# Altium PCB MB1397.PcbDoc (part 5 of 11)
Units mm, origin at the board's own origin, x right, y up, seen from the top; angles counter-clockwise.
Board outline 118.24 x 172.86 mm, 6 copper layers (Top Layer, L2_GND, L3_VCC, L4_SIG, L5_GND, Bottom Layer), stack 1.631 mm thick; 819 components, 632 nets, 2875 pads, 1523 vias.
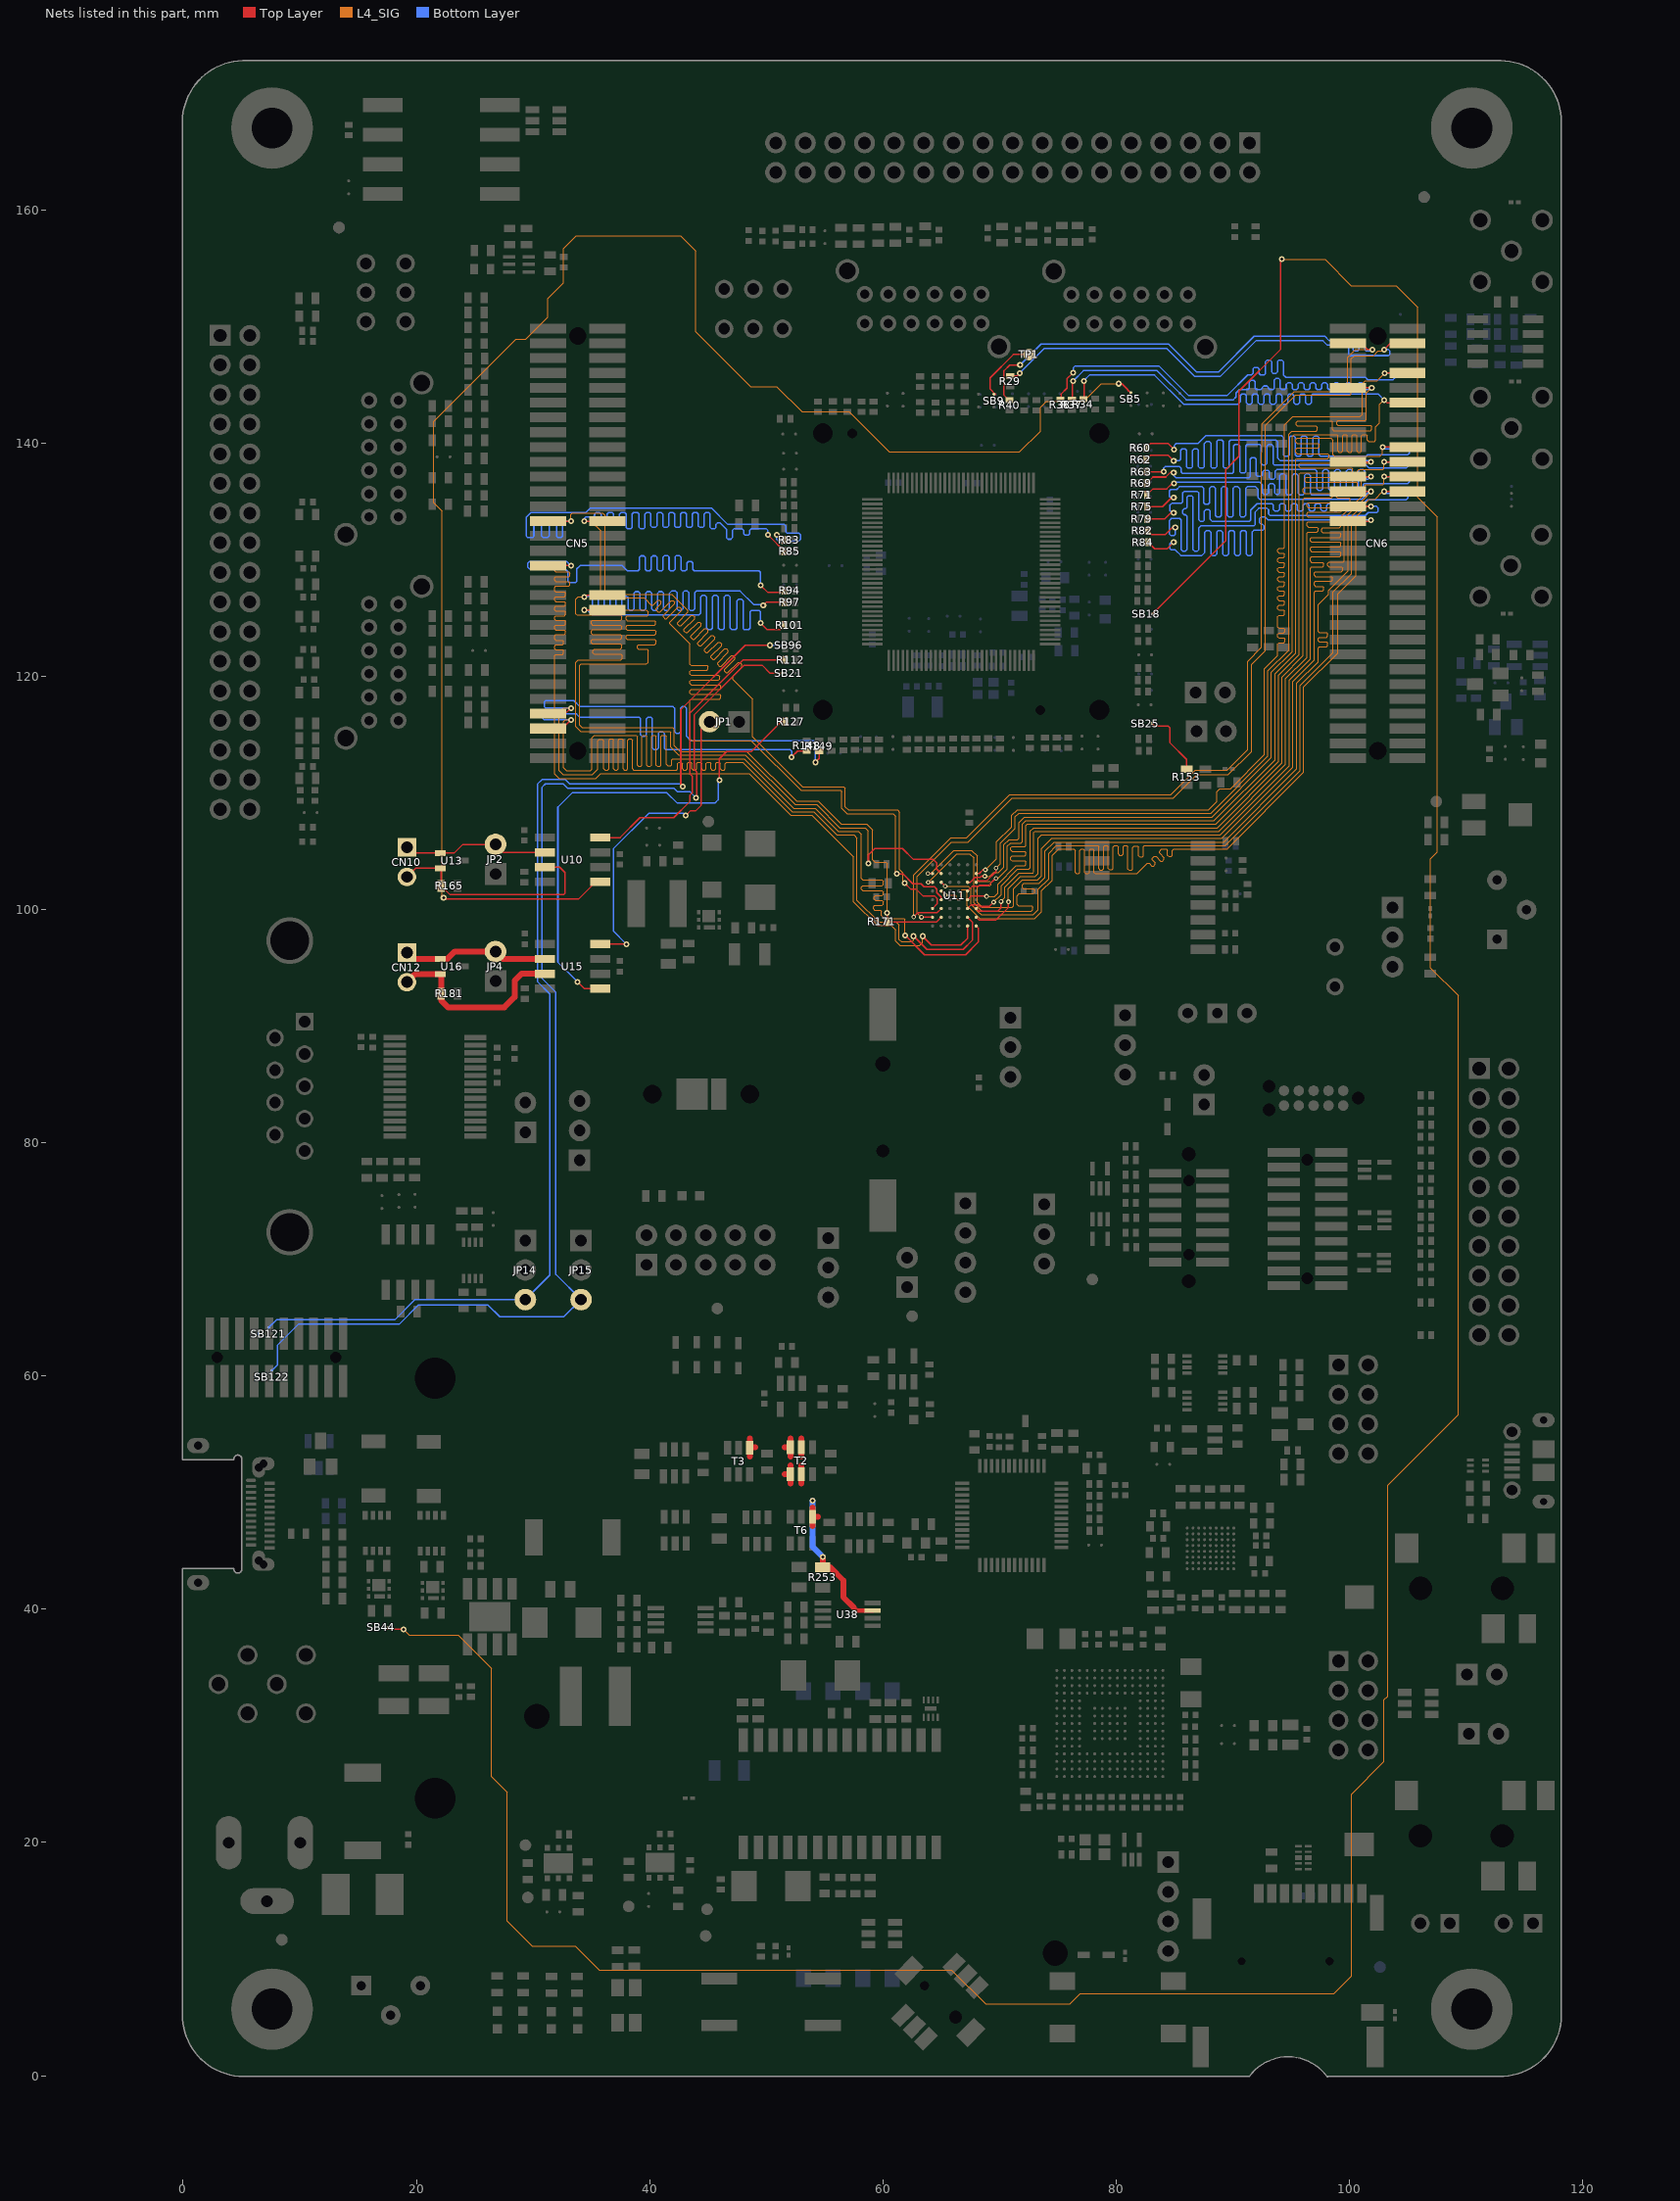
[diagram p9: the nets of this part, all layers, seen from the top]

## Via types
v1: diameter 0.508, hole 0.254, Top Layer to Bottom Layer, tented both sides, 1330 vias
v2: diameter 0.406, hole 0.203, Top Layer to Bottom Layer, tented both sides, 115 vias
v3: diameter 0.508, hole 0.254, Top Layer to Bottom Layer, 33 vias
v4: diameter 0.305, hole 0.152, Top Layer to Bottom Layer, tented both sides, 26 vias
v5: diameter 0.61, hole 0.305, Top Layer to Bottom Layer, tented both sides, 14 vias
v6: diameter 0.61, hole 0.33, Top Layer to Bottom Layer, tented both sides, 2 vias
v7: diameter 0.381, hole 0.203, Top Layer to Bottom Layer, tented both sides, 2 vias
v8: diameter 0.508, hole 0.203, Top Layer to Bottom Layer, tented both sides, 1 vias

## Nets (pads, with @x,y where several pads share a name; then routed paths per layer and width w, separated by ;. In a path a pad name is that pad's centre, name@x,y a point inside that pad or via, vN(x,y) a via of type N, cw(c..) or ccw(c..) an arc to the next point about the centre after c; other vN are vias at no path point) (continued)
CAL_D: R253.2 T2.1 T2.2 T2.5 T2.6 T3.4 T6.4 U38.3 | length 24
  Top Layer w0.381: 57.485,40.162 57.757,39.891 U38.3@59.098,39.891
  Top Layer w0.508: 48.58,53.094 T3.4@48.58,53.871 ; 48.58,54.648 T3.4@48.58,53.871 ; 49.058,53.871 T3.4@48.58,53.871 ; 51.58,51.57 T2.1@52.057,51.57 ; 51.58,53.871 T2.6@52.057,53.871 ; 52.057,50.792 T2.1@52.057,51.57 ; 52.057,52.349 T2.1@52.057,51.57 ; 52.057,53.094 T2.6@52.057,53.871 ; 52.057,54.648 T2.6@52.057,53.871 ; 53.007,50.792 53.007,52.349 ; 53.007,53.094 53.007,54.648 ; 53.957,47.147 T6.4@53.957,47.927 ; 53.957,48.705 T6.4@53.957,47.927 ; 54.435,47.925 T6.4@53.957,47.927 ; R253.2@54.836,43.594 R253.2@54.839,43.594 ; v1(54.839,44.498) R253.2@54.839,43.594 ; 57.485,40.162 56.614,41.034 56.614,42.466 55.486,43.594 R253.2@54.839,43.594
  Bottom Layer w0.508: v1(53.947,49.324) 53.947,45.387 v1(54.839,44.498)
CAN1H: CN12.1 JP4.2 U15.6 U16.1 | length 12.6
  Top Layer w0.508: CN12.1@19.186,96.307 19.718,95.773 22.672,95.773 23.292,96.393 JP4.2@26.782,96.394 27.417,95.758 U15.6@31.011,95.759
CAN1L: CN12.2 R181.1 U15.7 U16.2 | length 16.6
  Top Layer w0.508: CN12.2@19.186,93.767 CN12.2@19.186,93.767 19.893,94.473 U16.2@22.048,94.474 22.121,94.402 R181.1@22.121,92.786 ; R181.1@22.12,92.788 R181.1@22.121,92.786 ; U15.7@31.011,94.489 29.007,94.488 28.42,93.901 28.42,92.504 27.531,91.615 22.705,91.615 22.121,92.199 R181.1@22.121,92.786
CAN2H: CN10.1 JP2.2 U10.6 U13.1 | length 12.6
  Top Layer w0.127: CN10.1@19.186,105.33 19.68,104.833 23.226,104.833 23.975,105.583 JP2.2@26.782,105.584 27.465,104.899 U10.6@31.011,104.901
CAN2L: CN10.2 R165.1 U10.7 U13.2 | length 19.4
  Top Layer w0.127: CN10.2@19.186,102.79 CN10.2@19.186,102.79 19.931,103.533 22.05,103.533 22.121,103.462 R165.1@22.121,102.027 22.88,101.267 32.611,101.267 32.738,101.394 32.738,103.172 32.281,103.629 U10.7@31.011,103.631
CMOP6_OUT: SB9.1 TP1.1 | length 5.8
  Top Layer w0.127: SB9.1@69.642,144.178 69.187,144.633 69.187,145.59 71.183,147.587 TP1.1@72.517,147.588
CON1_CC1: JP15.3 SB21.2 SB122.2 | length 106.8
  Top Layer w0.127: v1(43.978,109.573) 43.978,109.611 44.041,109.675 44.041,111.808 43.812,112.037 43.812,116.665 48.1,120.952 49.629,120.952 50.315,120.269 SB21.2@51.387,120.269
  Bottom Layer w0.127: SB122.2@7.62,60.48 8.1,60.96 8.1,62.659 9.878,64.437 18.514,64.437 20.165,66.088 26.134,66.088 27.15,65.072 32.642,65.072 JP15.3@34.117,66.548 31.951,68.712 31.951,92.911 30.782,94.079 30.782,110.487 31.062,110.767 32.586,110.767 32.967,110.386 42.085,110.386 42.39,110.081 43.47,110.081 v1(43.978,109.573)
CON1_CC2: JP14.3 SB96.2 SB121.2 | length 98.8
  Top Layer w0.127: v1@42.669,110.716 42.669,117.14 48.186,122.657 v1(50.317,122.657)
  Bottom Layer w0.127: SB121.2@7.338,64.15 SB121.2@7.338,64.148 SB121.2@7.338,64.148 8.006,64.818 18.133,64.818 19.863,66.548 JP14.3@29.337,66.548 31.443,68.654 31.443,92.758 30.376,93.825 30.376,110.741 30.782,111.148 32.763,111.148 33.144,110.767 42.619,110.767 42.835,110.551 v1(42.835,110.538) ; v1(50.317,122.657) SB96.2@51.372,122.657
D0: CN6.4 R29.2 U11.B6 | length 120.6
  Top Layer w0.127: v2(63.294,99.334) U11.B6@64.249,99.335 ; R29.2@70.903,145.738 71.468,145.738 v1(71.727,145.997) ; v1(102.969,148.003) 103.505,148.539 CN6.4@104.965,148.541
  L4_SIG w0.102: v2(63.294,99.334) 62.939,99.69 62.939,102.817 65.885,105.763 67.282,105.763 71.067,109.548 84.884,109.548 86.891,111.554 89.617,111.554 91.618,113.553 91.618,121.031 92.784,122.197 92.784,141.501 95.4,144.117 100.073,144.117 100.15,144.193 100.15,147.216 100.429,147.495 102.08,147.495 102.461,147.876 102.842,147.876 v1(102.969,148.003)
  Bottom Layer w0.127: v1(71.727,145.997) 73.835,148.105 84.333,148.105 86.746,145.692 88.908,145.692 91.981,148.765 97.732,148.765 98.113,148.384 99.794,148.384 99.919,148.26 99.919,147.622 100.048,147.495 103.35,147.495 103.477,147.622 103.477,147.876 103.35,148.003 v1(102.969,148.003)
D1: CN6.3 R40.2 U11.C5 | length 123.9
  Top Layer w0.127: v2(62.634,99.362) 63.015,99.743 64.658,99.743 U11.C5@64.999,100.085 U11.C5@64.999,100.086 ; R40.2@70.902,143.579 70.823,143.657 70.381,144.097 70.381,146.2 70.863,146.682 v1(71.752,146.682) ; CN6.3@99.865,148.541 99.865,148.542 101.036,148.542 101.572,148.003 v1(101.953,148.003)
  L4_SIG w0.102: v2(62.634,99.362) 62.634,102.969 65.809,106.144 67.18,106.144 70.889,109.852 84.681,109.852 86.764,111.935 89.507,111.935 91.264,113.692 91.264,121.286 92.453,122.476 92.453,139.215 92.479,139.24 92.479,141.628 95.273,144.422 99.667,144.422 99.845,144.6 99.845,147.343 100.505,148.003 v1(101.953,148.003)
  Bottom Layer w0.127: v1(71.752,146.682) 73.556,148.486 84.493,148.486 86.906,146.073 88.75,146.073 91.824,149.146 97.889,149.146 98.27,148.765 100.173,148.765 100.3,148.638 100.3,148.003 100.427,147.876 100.681,147.876 100.808,148.003 100.808,148.638 100.935,148.765 101.189,148.765 101.318,148.636 101.318,148.003 101.445,147.876 101.826,147.876 v1(101.953,148.003)
D2: CN5.27 R83.2 U11.C6 | length 123.6
  Top Layer w0.127: CN5.27@31.285,133.301 v1(33.246,133.299) ; v1(50.899,132.128) 51.087,132.128 R83.2@51.522,131.695 ; v1(61.846,102.283) 62.405,101.724 62.862,101.724 63.421,101.166 64.412,101.166 64.64,100.937 64.64,100.477 64.249,100.086 U11.C6@64.249,100.085
  L4_SIG w0.102: v1(33.246,133.299) 33.246,133.883 33.348,133.985 35.961,133.985 36.167,133.779 36.167,127.302 36.446,127.023 41.907,127.023 43.284,125.646 43.284,125.504 42.385,124.605 42.385,124.463 42.53,124.318 42.672,124.318 43.571,125.217 43.713,125.217 43.858,125.072 43.858,124.93 42.962,124.031 42.962,123.889 43.104,123.744 43.249,123.744 44.145,124.64 44.29,124.64 44.432,124.498 44.432,124.353 43.536,123.457 43.536,123.312 43.68,123.167 43.823,123.167 44.722,124.066 44.864,124.066 45.009,123.922 45.009,123.779 44.11,122.88 44.11,122.738 44.254,122.593 44.399,122.593 45.296,123.492 45.441,123.492 45.583,123.347 45.583,123.203 44.686,122.306 44.686,122.161 44.831,122.019 44.973,122.019 45.87,122.916 46.015,122.916 46.159,122.771 46.159,122.629 45.26,121.73 45.26,121.587 45.405,121.442 45.547,121.442 46.446,122.342 46.589,122.342 46.733,122.197 46.733,122.055 45.837,121.155 45.837,121.013 45.979,120.868 46.124,120.868 47.02,121.765 47.165,121.765 47.307,121.623 47.307,121.478 46.411,120.581 46.411,120.437 46.556,120.292 46.698,120.292 47.597,121.191 47.739,121.191 47.902,121.028 47.902,120.774 47.14,120.012 47.14,119.733 48.816,118.057 48.816,114.805 53.109,110.513 56.639,110.513 56.779,110.373 56.779,108.811 57.059,108.532 61.237,108.532 61.44,108.328 61.44,103.426 61.719,103.147 61.719,102.41 v1(61.846,102.283)
  Bottom Layer w0.127: v1(33.246,133.299) 32.647,133.299 32.52,133.172 32.52,132.027 32.393,131.9 32.139,131.9 32.012,132.027 32.012,133.426 31.885,133.553 31.504,133.553 31.377,133.426 31.377,132.027 31.25,131.9 30.869,131.9 30.706,132.062 30.706,133.426 30.579,133.553 30.226,133.553 30.071,133.398 30.071,132.001 29.969,131.9 29.538,131.9 29.436,132.001 29.436,133.652 29.817,134.033 34.516,134.033 34.897,134.414 45.314,134.414 46.711,133.017 51.534,133.017 51.661,132.89 51.661,132.382 51.788,132.255 52.804,132.255 52.931,132.128 52.931,131.747 52.804,131.62 51.026,131.62 50.899,131.747 v1(50.899,132.128)
D3: CN5.28 R85.2 U11.D5 | length 124
  Top Layer w0.127: v1(34.389,133.299) CN5.28@36.385,133.301 ; v1(50.137,132.128) 50.264,132.001 50.264,131.999 51.544,130.724 R85.2@51.544,130.708 ; v1(61.173,103.058) 61.707,103.058 62.558,102.207 63.269,102.207 63.523,101.953 64.412,101.953 64.618,101.75 64.618,101.445 64.999,101.062 U11.D5@64.999,100.835
  L4_SIG w0.102: v1(34.389,133.299) 34.976,133.299 35.811,132.464 35.811,126.87 35.964,126.718 39.52,126.718 40.137,126.101 40.282,126.101 40.696,126.515 40.841,126.515 40.983,126.373 40.983,126.228 40.569,125.814 40.569,125.669 40.731,125.506 40.874,125.506 41.862,126.495 42.004,126.495 42.149,126.35 42.149,126.208 41.161,125.219 41.161,125.077 41.305,124.932 41.45,124.932 42.436,125.921 42.581,125.921 42.723,125.776 42.723,125.631 41.737,124.645 41.737,124.501 43.457,122.781 43.457,121.036 43.558,120.934 44.912,120.934 45.014,120.833 45.014,120.63 44.912,120.528 43.558,120.528 43.457,120.426 43.457,120.18 43.558,120.079 45.895,120.079 45.997,119.977 45.997,119.774 45.895,119.672 43.558,119.672 43.457,119.571 43.457,119.367 43.558,119.266 46.004,119.266 46.106,119.164 46.106,118.961 46.004,118.859 43.558,118.859 43.457,118.758 43.457,118.555 43.558,118.453 46.004,118.453 46.106,118.351 46.106,118.148 46.004,118.047 43.558,118.047 43.457,117.945 43.457,114.628 43.609,114.475 48.715,114.475 52.982,110.208 56.373,110.208 56.474,110.106 56.474,108.684 56.932,108.227 60.856,108.227 61.084,107.998 61.084,103.147 v1(61.173,103.058)
  Bottom Layer w0.127: v1(34.389,133.299) 34.389,133.525 34.516,133.652 35.151,133.652 35.278,133.779 35.278,133.906 35.405,134.033 35.707,134.033 35.834,133.906 35.834,133.703 35.961,133.576 36.215,133.576 36.342,133.703 36.342,133.906 36.469,134.033 36.784,134.033 36.911,133.906 36.911,133.449 37.038,133.322 37.292,133.322 37.419,133.449 37.419,133.906 37.546,134.033 37.856,134.033 37.983,133.906 37.983,132.763 38.11,132.636 38.364,132.636 38.491,132.763 38.491,133.906 38.618,134.033 38.961,134.033 39.088,133.906 39.088,132.763 39.215,132.636 39.469,132.636 39.596,132.763 39.596,133.906 39.723,134.033 39.977,134.033 40.104,133.906 40.104,132.89 40.231,132.763 40.485,132.763 40.612,132.89 40.612,133.906 40.739,134.033 40.993,134.033 41.12,133.906 41.12,132.89 41.247,132.763 41.501,132.763 41.628,132.89 41.628,133.906 41.755,134.033 42.009,134.033 42.136,133.906 42.136,132.89 42.263,132.763 42.517,132.763 42.644,132.89 42.644,133.906 42.771,134.033 43.025,134.033 43.152,133.906 43.152,132.89 43.279,132.763 43.533,132.763 43.66,132.89 43.66,133.906 43.787,134.033 44.041,134.033 44.168,133.906 44.168,132.89 44.295,132.763 44.549,132.763 44.676,132.89 44.676,133.906 44.803,134.033 45.057,134.033 45.184,133.906 45.184,132.763 45.311,132.636 45.565,132.636 45.692,132.763 45.692,133.017 45.819,133.144 46.045,133.144 46.579,132.611 46.579,131.874 46.706,131.747 46.96,131.747 47.087,131.874 47.087,132.509 47.214,132.636 47.937,132.636 48.064,132.509 48.064,132.212 48.191,132.085 48.445,132.085 48.572,132.212 48.572,132.509 48.699,132.636 50.01,132.636 50.137,132.509 v1(50.137,132.128)
D4: CN6.27 R84.1 U11.E5 | length 122.5
  Top Layer w0.127: U11.E5@64.999,101.585 v2(65.347,101.237) ; R84.1@82.737,131.489 82.738,131.488 83.292,130.934 84.376,130.934 v1(84.935,131.493) ; CN6.27@99.865,133.301 101.727,133.299 v1(101.826,133.398)
  L4_SIG w0.102: v2(65.347,101.237) 66.18,101.237 66.281,101.135 66.281,100.957 66.383,100.856 66.586,100.856 66.713,100.983 66.713,101.618 66.815,101.719 67.13,101.719 67.231,101.618 67.231,100.307 67.666,99.873 67.668,99.873 68.306,99.235 73.022,99.235 73.607,99.819 73.607,101.597 74.521,102.512 74.521,104.62 75.08,105.179 76.375,105.179 76.477,105.077 76.477,103.172 76.578,103.071 76.782,103.071 76.883,103.172 76.883,105.077 76.985,105.179 77.188,105.179 77.29,105.077 77.29,103.172 77.391,103.071 77.594,103.071 77.696,103.172 77.696,105.077 77.798,105.179 78.001,105.179 78.102,105.077 78.102,103.172 78.204,103.071 81.785,103.071 82.68,103.965 82.822,103.965 83.061,103.726 83.203,103.726 83.348,103.871 83.348,104.013 83.109,104.252 83.109,104.394 83.271,104.557 83.416,104.557 83.817,104.155 83.962,104.155 84.104,104.297 84.104,104.442 83.703,104.844 83.703,104.988 83.894,105.179 84.31,105.179 84.412,105.077 84.412,104.645 84.513,104.544 84.717,104.544 84.818,104.645 84.818,105.077 84.92,105.179 89.502,105.179 96.086,111.763 96.086,119.07 99.007,121.991 99.007,127.079 100.559,128.626 100.559,132.958 100.9,133.299 101.727,133.299 v1(101.826,133.398)
  Bottom Layer w0.127: v1(84.935,131.493) 84.712,131.493 84.585,131.366 84.585,130.97 84.712,130.843 85.047,130.843 85.54,130.35 87.348,130.35 87.602,130.604 87.602,132.357 87.729,132.484 87.983,132.484 88.11,132.357 88.11,130.477 88.237,130.35 88.491,130.35 88.618,130.477 88.618,132.357 88.745,132.484 88.999,132.484 89.126,132.357 89.126,130.477 89.253,130.35 89.507,130.35 89.634,130.477 89.634,132.357 89.761,132.484 90.015,132.484 90.142,132.357 90.142,130.477 90.269,130.35 90.523,130.35 90.65,130.477 90.65,132.357 90.777,132.484 91.031,132.484 91.158,132.357 91.158,130.477 91.285,130.35 91.539,130.35 91.666,130.477 91.666,132.382 91.793,132.509 92.555,132.509 92.682,132.636 92.682,132.89 92.555,133.017 92.428,133.017 92.301,133.144 92.301,133.546 92.428,133.673 92.756,133.673 93.033,133.398 v1(101.826,133.398)
D5: CN6.25 R82.1 U11.F5 | length 122.6
  Top Layer w0.127: U11.F5@64.999,102.335 v2(65.341,101.994) ; R82.1@82.7,132.48 83.05,132.128 84.173,132.128 84.808,132.763 v1(85.062,132.763) ; CN6.25@99.865,134.571 v1(101.826,134.569)
  L4_SIG w0.102: v2(65.341,101.994) 67.318,101.994 67.536,101.775 67.536,100.432 68.097,99.873 68.1,99.873 68.412,99.56 72.865,99.56 73.302,99.997 73.302,101.724 74.216,102.639 74.216,104.823 74.877,105.484 78.407,105.484 78.509,105.382 78.509,103.502 78.61,103.401 78.814,103.401 78.915,103.502 78.915,105.382 79.017,105.484 79.22,105.484 79.322,105.382 79.322,103.523 79.423,103.424 79.626,103.424 79.728,103.523 79.728,105.357 79.855,105.484 80.084,105.484 80.185,105.382 80.185,104.747 80.287,104.645 80.49,104.645 80.592,104.747 80.592,105.382 80.693,105.484 80.904,105.484 81.006,105.382 81.006,103.477 81.107,103.375 81.31,103.375 81.412,103.477 81.412,105.331 81.542,105.458 81.824,105.458 81.925,105.357 81.925,104.595 82.027,104.493 82.23,104.493 82.332,104.595 82.332,105.382 82.433,105.484 89.355,105.484 95.781,111.91 95.781,119.225 98.6,122.044 98.6,127.226 100.175,128.801 100.175,133.271 101.473,134.569 v1(101.826,134.569)
  Bottom Layer w0.127: v1(85.062,132.763) 85.062,132.179 84.935,132.052 84.706,132.052 84.579,132.179 84.579,133.373 84.732,133.525 85.443,133.525 85.57,133.398 85.57,130.858 85.697,130.731 85.951,130.731 86.078,130.858 86.078,133.721 85.951,133.848 85.824,133.848 85.697,133.975 85.697,134.229 85.824,134.356 85.951,134.356 86.078,134.483 86.078,135.354 86.205,135.481 86.459,135.481 86.586,135.354 86.586,130.858 86.713,130.731 86.967,130.731 87.094,130.858 87.094,132.738 87.246,132.89 91.793,132.89 91.92,133.017 91.92,134.092 92.222,134.394 92.936,134.394 93.063,134.267 93.063,133.906 93.19,133.779 101.349,133.779 101.603,134.033 102.334,134.033 102.461,134.16 102.461,134.414 102.306,134.569 v1(101.826,134.569)
D6: CN6.24 R79.1 U11.F6 | length 121.9
  Top Layer w0.127: v2(63.878,102.334) U11.F6@64.249,102.335 ; R79.1@82.661,133.473 84.145,133.472 84.706,134.033 v1(84.935,134.033) ; v1(102.969,135.842) 104.965,135.842 CN6.24@104.965,135.841
  L4_SIG w0.102: v2(63.878,102.334) 66.317,104.772 67.434,104.772 67.788,104.422 67.788,100.561 68.483,99.865 72.713,99.865 72.845,99.997 72.845,100.2 72.743,100.302 71.625,100.302 71.498,100.429 71.498,101.166 71.676,101.343 72.895,101.343 72.997,101.445 72.997,101.674 72.895,101.775 72.057,101.775 71.956,101.877 71.956,102.105 72.083,102.232 73.378,102.232 73.911,102.766 73.911,105.024 74.673,105.788 89.205,105.788 95.476,112.06 95.476,119.403 97.312,121.239 97.312,122.423 97.414,122.525 98.041,122.525 98.143,122.626 98.143,122.829 98.041,122.931 97.414,122.931 97.312,123.033 97.312,123.236 97.414,123.337 98.041,123.337 98.143,123.439 98.143,123.642 98.041,123.744 97.414,123.744 97.312,123.845 97.312,126.134 98.194,127.015 98.194,127.376 99.87,129.055 99.87,133.398 101.347,134.874 101.405,134.874 101.708,135.176 102.182,135.176 102.847,135.842 v1(102.969,135.842)
  Bottom Layer w0.127: v1(84.935,134.033) 84.783,134.033 84.605,134.211 84.605,134.668 84.757,134.821 85.57,134.821 85.697,134.948 85.697,135.71 85.849,135.862 86.942,135.862 87.094,135.71 87.094,133.398 87.221,133.271 87.424,133.271 87.551,133.398 87.551,134.16 87.678,134.287 87.932,134.287 88.059,134.16 88.059,133.449 88.237,133.271 91.412,133.271 91.539,133.398 91.539,134.249 92.085,134.795 93.355,134.795 93.482,134.668 93.482,134.287 93.609,134.16 93.863,134.16 93.99,134.287 93.99,134.668 94.117,134.795 94.371,134.795 94.498,134.668 94.498,134.287 94.625,134.16 94.879,134.16 95.006,134.287 95.006,134.668 95.133,134.795 95.387,134.795 95.514,134.668 95.514,134.287 95.641,134.16 95.895,134.16 96.022,134.287 96.022,134.668 96.149,134.795 96.403,134.795 96.53,134.668 96.53,134.287 96.657,134.16 96.911,134.16 97.038,134.287 97.038,134.668 97.165,134.795 97.419,134.795 97.546,134.668 97.546,134.287 97.673,134.16 97.927,134.16 98.054,134.287 98.054,134.668 98.181,134.795 98.435,134.795 98.562,134.668 98.562,134.287 98.689,134.16 98.943,134.16 99.07,134.287 99.07,134.668 99.197,134.795 99.451,134.795 99.578,134.668 99.578,134.287 99.705,134.16 99.959,134.16 100.086,134.287 100.086,134.668 100.213,134.795 100.467,134.795 100.594,134.668 100.594,134.287 100.721,134.16 101.191,134.16 101.318,134.287 101.318,134.922 101.521,135.125 104.874,135.125 105.001,135.252 105.001,135.557 104.874,135.684 103.124,135.684 v1(102.969,135.842)
D7: CN6.23 R75.1 U11.G6 | length 121.9
  Top Layer w0.127: v2(63.853,103.086) 64.249,103.086 U11.G6@64.249,103.085 ; R75.1@82.658,134.536 82.659,134.536 83.965,134.536 84.732,135.303 v1(84.935,135.303) ; CN6.23@99.865,135.841 99.865,135.842 v1(101.826,135.842)
  L4_SIG w0.102: v2(63.853,103.086) 64.094,103.086 66.088,105.077 67.612,105.077 68.095,104.595 68.095,102.527 68.196,102.426 69.162,102.426 69.263,102.324 69.263,102.121 69.162,102.019 68.196,102.019 68.095,101.918 68.095,100.612 68.506,100.2 71.09,100.2 71.194,100.302 71.194,101.775 71.956,102.537 73.251,102.537 73.607,102.893 73.607,105.23 74.47,106.093 89.047,106.093 95.138,112.184 95.138,119.543 96.975,121.379 96.975,127.201 97.076,127.302 97.686,127.302 97.787,127.404 97.787,127.607 97.686,127.709 97.076,127.709 96.975,127.81 96.975,128.039 97.076,128.14 98.448,128.14 98.549,128.242 98.549,128.445 98.448,128.547 97.076,128.547 96.975,128.648 96.975,128.852 97.076,128.953 99.291,128.953 99.413,129.075 99.413,129.278 99.311,129.38 98.245,129.38 98.143,129.482 98.143,129.685 98.245,129.786 99.464,129.786 99.565,129.888 99.565,133.524 101.22,135.179 ; 101.222,135.179 101.826,135.783 v1(101.826,135.842)
  Bottom Layer w0.127: v1(84.935,135.303) 84.681,135.303 84.554,135.43 84.554,135.885 84.681,136.012 85.189,136.012 85.42,136.243 87.368,136.243 87.495,136.116 87.495,134.871 87.622,134.744 87.876,134.744 88.003,134.871 88.003,136.116 88.13,136.243 88.384,136.243 88.511,136.116 88.511,133.779 88.638,133.652 88.892,133.652 89.019,133.779 89.019,136.116 89.146,136.243 89.4,136.243 89.527,136.116 89.527,133.779 89.654,133.652 89.908,133.652 90.035,133.779 90.035,136.116 90.162,136.243 90.447,136.243 90.594,136.096 90.594,133.795 90.721,133.668 90.975,133.668 91.102,133.795 91.102,136.111 91.234,136.243 91.945,136.243 92.174,136.014 92.174,135.303 92.301,135.176 101.034,135.176 101.699,135.842 v1(101.826,135.842)
D8: CN6.22 R71.1 U11.B1 | length 121
  Top Layer w0.127: U11.B1@67.999,99.335 68.001,99.334 68.224,99.108 69.695,99.108 70.762,100.175 v2(70.762,100.658) ; R71.1@82.644,135.56 83.155,136.065 84.331,136.065 84.788,136.522 v1(84.96,136.522) ; v1(102.969,137.112) 104.965,137.112 CN6.22@104.965,137.111
  L4_SIG w0.102: v2(70.762,100.658) 70.762,101.801 71.803,102.842 73.048,102.842 73.302,103.096 73.302,106.119 73.581,106.398 88.92,106.398 94.833,112.311 94.833,119.67 96.644,121.481 96.644,129.258 96.746,129.36 97.686,129.36 97.787,129.461 97.787,129.664 97.686,129.766 96.746,129.766 96.644,129.868 96.644,130.15 96.746,130.251 99.159,130.251 99.261,130.353 99.261,130.581 99.159,130.683 96.746,130.683 96.644,130.785 96.644,130.988 96.746,131.089 99.159,131.089 99.261,131.191 99.261,131.394 99.159,131.496 96.746,131.496 96.644,131.597 96.644,131.801 96.746,131.902 99.159,131.902 99.261,132.004 99.261,132.207 99.159,132.309 97.711,132.309 97.61,132.41 97.61,132.613 97.711,132.715 99.134,132.715 99.261,132.842 99.261,133.65 101.094,135.484 ; 101.095,135.484 101.318,135.707 101.318,136.345 101.42,136.446 102.867,136.446 102.969,136.548 v1(102.969,137.112)
  Bottom Layer w0.127: v1(84.96,136.522) 85.062,136.624 92.326,136.624 92.555,136.395 92.555,135.738 92.682,135.611 92.936,135.611 93.063,135.738 93.063,136.395 93.19,136.522 93.444,136.522 93.571,136.395 93.571,135.738 93.698,135.611 93.901,135.611 94.028,135.738 94.028,137.208 94.155,137.335 94.412,137.335 94.536,137.208 94.536,135.684 94.663,135.557 94.968,135.557 95.095,135.684 95.095,137.208 95.222,137.335 95.476,137.335 95.603,137.208 95.603,135.684 95.73,135.557 96.009,135.557 96.136,135.684 96.136,137.208 96.263,137.335 96.517,137.335 96.644,137.208 96.644,135.684 96.771,135.557 100.876,135.557 101.191,135.872 101.191,136.446 101.267,136.522 105.001,136.522 105.128,136.649 105.128,136.985 105.001,137.112 v1(102.969,137.112)
D9: CN6.21 R69.1 U11.C1 | length 120.3
  Top Layer w0.127: U11.C1@67.999,100.085 68.001,100.086 68.227,99.858 69.835,99.858 70.127,100.15 v2(70.127,100.683) ; R69.1@82.619,136.55 83.149,137.081 84.249,137.081 84.63,137.462 v1(84.935,137.462) ; CN6.21@99.865,137.111 99.865,137.112 v1(101.826,137.112)
  L4_SIG w0.102: v2(70.127,100.683) 70.457,101.013 70.457,101.925 71.676,103.147 72.87,103.147 72.946,103.223 72.946,106.601 73.048,106.703 88.793,106.703 94.529,112.438 94.529,119.797 96.34,121.608 96.34,132.265 96.441,132.367 97.203,132.367 97.305,132.469 97.305,132.672 97.203,132.773 96.467,132.773 96.34,132.9 96.34,133.149 96.441,133.251 98.854,133.251 98.956,133.353 98.956,133.556 98.854,133.657 96.441,133.657 96.34,133.759 96.34,133.962 96.441,134.064 99.235,134.064 99.337,134.165 99.337,134.369 99.235,134.47 96.441,134.47 96.34,134.572 96.34,134.775 96.441,134.877 99.972,134.877 100.073,134.978 100.073,135.202 99.972,135.303 98.981,135.303 98.854,135.43 98.854,135.659 98.956,135.76 100.81,135.76 101.013,135.964 101.013,137.01 101.115,137.112 v1(101.826,137.112)
  Bottom Layer w0.127: v1(84.935,137.462) 84.935,137.208 85.138,137.005 91.356,137.005 91.483,137.132 91.483,138.605 91.61,138.732 91.864,138.732 91.991,138.605 91.991,137.259 92.118,137.132 92.428,137.132 92.555,137.259 92.555,137.513 92.682,137.64 93.012,137.64 93.139,137.513 93.139,137.03 93.266,136.903 93.52,136.903 93.647,137.03 93.647,137.589 93.774,137.716 97.071,137.716 97.198,137.589 97.198,136.065 97.325,135.938 97.579,135.938 97.706,136.065 97.706,137.589 97.833,137.716 98.087,137.716 98.214,137.589 98.214,136.065 98.341,135.938 98.595,135.938 98.722,136.065 98.722,137.589 98.849,137.716 99.103,137.716 99.23,137.589 99.23,136.065 99.357,135.938 99.611,135.938 99.738,136.065 99.738,137.589 99.865,137.716 100.119,137.716 100.246,137.589 100.246,136.065 100.373,135.938 100.63,135.938 100.757,136.065 100.757,137.589 100.884,137.716 101.191,137.716 101.318,137.589 101.318,137.038 101.445,136.911 101.625,136.911 v1(101.826,137.112)
D10: CN6.20 R63.1 U11.C2 | length 120.8
  Top Layer w0.127: U11.C2@67.249,100.085 67.249,100.086 67.579,100.416 68.138,100.416 68.301,100.251 69.111,100.251 v2(69.492,100.632) ; R63.1@82.599,137.541 v1(84.071,137.541) ; v1(102.969,138.382) 104.965,138.382 CN6.20@104.965,138.381
  L4_SIG w0.102: v2(69.492,100.632) 70.152,101.293 70.152,102.052 71.552,103.452 72.514,103.452 72.641,103.579 72.641,106.726 72.921,107.008 88.666,107.008 94.224,112.565 94.224,119.946 96.035,121.757 96.035,135.181 96.136,135.283 98.448,135.283 98.549,135.385 98.549,135.588 98.448,135.689 96.136,135.689 96.035,135.791 96.035,136.065 96.136,136.167 100.581,136.167 100.683,136.268 100.683,136.535 100.581,136.637 96.289,136.637 96.187,136.738 96.187,136.942 96.289,137.043 100.581,137.043 100.683,137.145 100.683,137.589 100.81,137.716 102.867,137.716 102.969,137.818 v1(102.969,138.382)
  Bottom Layer w0.127: v1(84.071,137.541) 84.071,137.843 84.198,137.97 85.443,137.97 85.57,137.843 85.57,137.513 85.697,137.386 89.939,137.386 90.068,137.516 90.068,139.748 90.195,139.875 90.467,139.875 90.594,139.748 90.594,137.549 90.706,137.437 90.99,137.437 91.102,137.549 91.102,139.748 91.229,139.875 92.301,139.875 92.428,139.748 92.428,138.25 92.555,138.123 92.809,138.123 92.936,138.25 92.936,139.748 93.063,139.875 93.317,139.875 93.444,139.748 93.444,138.224 93.571,138.097 101.445,138.097 101.699,137.843 104.874,137.843 105.001,137.97 105.001,138.224 104.844,138.382 v1(102.969,138.382)
D11: CN6.19 R62.1 U11.D2 | length 119.6
  Top Layer w0.127: U11.D2@67.249,100.835 67.249,100.835 67.254,100.835 67.584,101.166 68.844,101.166 v2(68.882,101.128) ; R62.1@82.568,138.582 82.923,138.935 84.478,138.935 v1(84.935,138.478) ; CN6.19@99.865,138.381 99.865,138.382 v1(101.826,138.382)
  L4_SIG w0.102: v2(68.882,101.128) 69.555,101.128 69.847,101.42 69.847,102.179 71.425,103.756 72.184,103.756 72.26,103.833 72.26,104.074 72.159,104.176 71.067,104.176 70.965,104.277 70.965,104.48 71.067,104.582 72.159,104.582 72.26,104.684 72.26,104.887 72.159,104.988 71.067,104.988 70.965,105.09 70.965,105.293 71.067,105.395 72.159,105.395 72.26,105.496 72.26,107.211 72.362,107.312 88.539,107.312 93.919,112.692 93.919,120.073 95.705,121.859 95.705,137.348 95.806,137.45 100.175,137.45 100.277,137.551 100.277,137.754 100.175,137.856 95.806,137.856 95.705,137.958 95.705,138.173 95.806,138.275 101.719,138.275 v1(101.826,138.382)
  Bottom Layer w0.127: v1(84.935,138.478) 85.4,138.478 85.527,138.605 85.527,139.367 85.654,139.494 85.908,139.494 86.035,139.367 86.035,137.97 86.162,137.843 86.418,137.843 86.543,137.97 86.543,139.367 86.67,139.494 86.924,139.494 87.051,139.367 87.051,137.97 87.178,137.843 87.434,137.843 87.559,137.97 87.559,139.959 87.729,140.129 87.983,140.129 88.11,140.002 88.11,137.97 88.237,137.843 88.491,137.843 88.618,137.97 88.618,140.129 88.745,140.256 89.052,140.256 89.179,140.129 89.179,137.97 89.306,137.843 89.56,137.843 89.687,137.97 89.687,140.129 89.814,140.256 93.698,140.256 93.825,140.129 93.825,138.732 94.079,138.478 101.73,138.478 v1(101.826,138.382)
D12: CN6.18 R60.1 U11.E2 | length 119.7
  Top Layer w0.127: U11.E2@67.249,101.585 67.645,101.981 68.176,101.981 68.252,102.057 69.045,102.057 69.652,102.664 v2(69.695,102.664) ; R60.1@82.549,139.573 82.931,139.954 84.45,139.954 84.958,139.446 v1(84.963,139.446) ; v1(102.842,139.652) 104.965,139.652 CN6.18@104.965,139.651
  L4_SIG w0.102: v2(69.695,102.664) 69.847,102.664 70.66,103.477 70.66,105.42 70.94,105.7 71.854,105.7 71.956,105.801 71.956,107.335 72.235,107.617 88.392,107.617 93.614,112.84 93.614,120.2 95.4,121.986 95.4,138.6 95.476,138.676 98.143,138.676 98.245,138.778 98.245,138.981 98.143,139.083 95.507,139.083 95.4,139.189 95.4,139.464 95.501,139.565 97.305,139.565 97.406,139.667 97.406,139.87 97.305,139.972 95.501,139.972 95.4,140.073 95.4,140.307 95.501,140.409 98.397,140.409 98.6,140.205 98.6,139.012 98.753,138.859 102.613,138.859 102.842,139.088 v1(102.842,139.652)
  Bottom Layer w0.127: v1(84.963,139.446) 84.963,139.776 85.151,139.964 87.023,139.964 87.696,140.637 94.168,140.637 94.333,140.472 94.333,138.986 94.46,138.859 94.714,138.859 94.841,138.986 94.841,140.472 94.968,140.599 95.222,140.599 95.349,140.472 95.349,138.986 95.476,138.859 95.73,138.859 95.857,138.986 95.857,140.472 95.984,140.599 96.238,140.599 96.365,140.472 96.365,138.986 96.492,138.859 96.746,138.859 96.873,138.986 96.873,140.472 97,140.599 97.254,140.599 97.381,140.472 97.381,138.986 97.508,138.859 101.445,138.859 101.572,138.986 105.001,138.986 105.128,139.113 105.128,139.367 105.001,139.494 102.997,139.494 v1(102.842,139.652)
D13: CN6.12 R34.2 U11.F2 | length 120.6
  Top Layer w0.127: U11.F2@67.249,102.335 67.485,102.334 67.894,102.743 68.311,102.743 68.423,102.855 v2(68.743,102.855) ; v1(77.213,145.329) 77.213,145.311 77.267,145.258 R34.2@77.267,143.647 ; v1(102.969,143.685) 103.193,143.462 104.965,143.462 CN6.12@104.965,143.461
  L4_SIG w0.102: v2(68.743,102.855) 69.149,102.855 69.466,103.172 69.898,103.172 70.355,103.629 70.355,105.545 70.813,106.004 71.549,106.004 71.651,106.106 71.651,107.462 72.108,107.922 88.212,107.922 93.309,113.02 93.309,120.327 95.095,122.113 95.095,140.536 95.273,140.713 98.905,140.713 99.007,140.612 99.007,139.316 99.108,139.215 99.311,139.215 99.413,139.316 99.413,140.612 99.515,140.713 99.718,140.713 99.819,140.612 99.819,139.316 99.921,139.215 100.124,139.215 100.226,139.316 100.226,140.612 100.327,140.713 100.531,140.713 100.632,140.612 100.632,139.316 100.734,139.215 100.937,139.215 101.039,139.316 101.039,140.612 101.14,140.713 101.443,140.713 101.544,140.612 101.544,140.231 101.646,140.129 102.156,140.129 102.258,140.231 102.258,141.399 102.588,141.729 102.588,143.304 v1(102.969,143.685)
  Bottom Layer w0.127: v1(77.213,145.329) 77.701,145.819 83.289,145.819 85.778,143.33 90.421,143.33 90.65,143.558 90.65,144.066 90.777,144.193 91.029,144.193 91.156,144.066 91.156,143.459 91.283,143.332 91.537,143.332 91.664,143.459 91.664,144.066 91.791,144.193 92.045,144.193 92.172,144.066 92.172,143.459 92.299,143.332 92.553,143.332 92.68,143.459 92.68,144.066 92.807,144.193 93.061,144.193 93.188,144.066 93.188,143.459 93.315,143.332 93.569,143.332 93.696,143.459 93.696,144.066 93.823,144.193 94.077,144.193 94.204,144.066 94.204,143.459 94.331,143.332 94.585,143.332 94.712,143.459 94.712,144.066 94.839,144.193 95.093,144.193 95.22,144.066 95.22,143.459 95.347,143.332 95.601,143.332 95.728,143.459 95.728,144.066 95.855,144.193 96.109,144.193 96.236,144.066 96.236,143.459 96.363,143.332 96.617,143.332 96.744,143.459 96.744,144.066 96.871,144.193 102.459,144.193 v1(102.969,143.685)
D14: CN6.9 R37.2 U11.F1 | length 121.5
  Top Layer w0.127: U11.F1@67.999,102.335 68.001,102.334 68.105,102.438 68.885,102.438 69.695,103.248 v2(69.695,103.553) ; R37.2@76.251,143.624 76.251,145.263 76.312,145.324 v1(76.312,145.329) ; CN6.9@99.865,144.731 99.865,144.732 v1(101.902,144.732)
  L4_SIG w0.102: v2(69.695,103.553) 70.051,103.909 70.051,105.672 71.346,106.967 71.346,107.947 71.651,108.252 88.11,108.252 93.005,113.147 93.005,120.454 94.79,122.24 94.79,140.739 95.07,141.018 97.152,141.018 97.254,141.12 97.254,141.323 97.127,141.45 95.527,141.45 95.425,141.552 95.425,141.755 95.552,141.882 98.448,141.882 98.524,141.806 98.524,141.171 98.626,141.069 101.801,141.069 101.902,141.171 101.902,141.407 101.801,141.508 99.007,141.508 98.905,141.61 98.905,141.813 99.007,141.915 101.343,141.915 101.445,142.016 101.445,144.275 v1(101.902,144.732)
  Bottom Layer w0.127: v1(76.312,145.329) 76.319,145.329 77.188,146.2 83.515,146.2 86.004,143.711 90.04,143.711 90.269,143.939 90.269,144.29 90.554,144.574 91.277,144.574 91.404,144.701 91.404,145.247 91.531,145.374 91.785,145.374 91.912,145.247 91.912,144.701 92.039,144.574 92.4,144.574 92.527,144.701 92.527,144.765 92.654,144.892 92.908,144.892 93.035,144.765 93.035,144.701 93.162,144.574 93.431,144.574 93.558,144.701 93.558,145.405 93.685,145.532 93.939,145.532 94.066,145.405 94.066,144.701 94.193,144.574 94.447,144.574 94.574,144.701 94.574,145.024 94.701,145.151 94.955,145.151 95.082,145.024 95.082,144.701 95.209,144.574 95.463,144.574 95.59,144.701 95.59,145.024 95.717,145.151 95.971,145.151 96.098,145.024 96.098,144.701 96.225,144.574 96.479,144.574 96.606,144.701 96.606,145.024 96.733,145.151 96.987,145.151 97.114,145.024 97.114,144.701 97.241,144.574 97.495,144.574 97.622,144.701 97.622,145.024 97.749,145.151 98.003,145.151 98.13,145.024 98.13,144.701 98.257,144.574 98.511,144.574 98.638,144.701 98.638,145.024 98.765,145.151 99.019,145.151 99.146,145.024 99.146,144.701 99.273,144.574 99.527,144.574 99.654,144.701 99.654,145.024 99.781,145.151 100.035,145.151 100.162,145.024 100.162,144.701 100.289,144.574 100.543,144.574 100.67,144.701 100.67,145.024 100.797,145.151 101.051,145.151 101.178,145.024 101.178,144.701 101.305,144.574 101.745,144.574 v1(101.902,144.732)
D15: CN6.8 R38.2 U11.G1 | length 121.8
  Top Layer w0.127: U11.G1@67.999,103.085 68.001,103.086 68.26,103.086 68.577,103.401 v2(68.781,103.401) ; R38.2@75.26,143.617 75.26,144.17 75.791,144.701 75.791,145.514 v1(76.312,146.035) ; v1(103.033,146.002) 104.965,146.002 CN6.8@104.965,146.001
  L4_SIG w0.102: v2(68.781,103.401) 69.746,104.366 69.746,105.799 71.041,107.094 71.041,108.074 71.524,108.557 87.907,108.557 88.628,109.278 88.628,110.117 88.882,110.368 89.794,110.368 92.7,113.274 92.7,120.64 93.85,121.79 93.85,122.779 93.952,122.88 94.384,122.88 94.485,122.982 94.485,123.185 94.384,123.287 93.952,123.287 93.85,123.388 93.85,123.619 93.952,123.721 94.358,123.721 94.46,123.822 94.46,124.026 94.358,124.127 93.952,124.127 93.85,124.229 93.85,125.118 93.952,125.219 94.333,125.219 94.435,125.321 94.435,125.58 94.333,125.682 93.952,125.682 93.85,125.783 93.85,125.987 93.952,126.088 94.333,126.088 94.435,126.19 94.435,126.393 94.333,126.495 93.952,126.495 93.85,126.596 93.85,126.799 93.952,126.901 94.333,126.901 94.435,127.003 94.435,127.206 94.333,127.307 93.952,127.307 93.85,127.409 93.85,127.612 93.952,127.714 94.333,127.714 94.435,127.815 94.435,128.019 94.333,128.12 93.952,128.12 93.85,128.222 93.85,128.425 93.952,128.527 94.333,128.527 94.435,128.628 94.435,128.831 94.333,128.933 93.952,128.933 93.85,129.035 93.85,129.238 93.952,129.339 94.333,129.339 94.435,129.441 94.435,129.644 94.333,129.746 93.952,129.746 93.85,129.847 93.85,130.051 93.952,130.152 94.333,130.152 94.435,130.254 94.435,130.457 94.333,130.559 93.952,130.559 93.85,130.66 93.85,130.863 93.952,130.965 94.333,130.965 94.435,131.067 94.435,141.552 95.146,142.263 100.912,142.263 101.089,142.441 101.089,145.082 101.343,145.336 102.37,145.336 v1(103.033,146.002)
  Bottom Layer w0.127: v1(76.312,146.035) 76.312,146.454 76.439,146.581 83.693,146.581 86.182,144.092 89.532,144.092 91.285,145.844 91.603,145.844 91.73,145.971 91.73,146.352 91.857,146.479 92.111,146.479 92.238,146.352 92.238,145.971 92.365,145.844 92.682,145.844 92.809,145.971 92.809,146.987 92.936,147.114 93.19,147.114 93.317,146.987 93.317,146.098 93.444,145.971 93.698,145.971 93.825,146.098 93.825,146.987 93.952,147.114 94.206,147.114 94.333,146.987 94.333,145.844 94.557,145.621 101.376,145.621 101.572,145.425 103.731,145.425 103.858,145.552 103.858,145.875 103.731,146.002 v1(103.033,146.002)
DAC: R153.2 SB25.1 | length 5.8
  Top Layer w0.127: SB25.1@83.05,115.951 83.256,115.745 84.427,115.745 84.618,115.555 84.618,114.285 86.032,112.87 R153.2@86.034,112.042
DISCHARGE: SB18.2 SB44.1 | length 306.1
  Top Layer w0.127: 17.49,38.275 v1(18.895,38.275) ; SB18.2@83.125,125.324 83.124,125.364 89.38,131.62 89.38,137.716 90.523,138.859 90.523,144.447 94.079,148.003 94.079,155.649 v1(94.181,155.75)
  L4_SIG w0.102: v1(18.895,38.275) 19.378,37.793 23.569,37.793 26.441,34.92 26.441,25.651 27.785,24.308 27.785,13.256 29.944,11.097 33.627,11.097 35.659,9.065 65.89,9.065 68.809,6.147 76.048,6.147 76.934,7.033 98.651,7.033 100.175,8.557 100.175,24.145 102.969,26.939 102.969,32.248 103.273,32.551 103.273,50.644 109.319,56.69 109.319,92.631 106.957,94.993 106.957,101.2 ; v1(94.181,155.75) 97.894,155.75 100.155,153.49 103.985,153.49 105.839,151.635 105.839,135.354 107.541,133.652 107.541,104.95 106.957,104.366 106.957,101.2 ; 106.929,101.2 106.957,101.2
FDCAN1_RX: JP1.2 U15.4 | length 27.5
  Top Layer w0.127: U15.4@35.761,97.029 v1(38.019,97.028) ; v1(43.101,108.074) 43.508,108.481 43.965,108.481 44.422,108.938 44.422,115.522 JP1.2@44.955,116.055
  Bottom Layer w0.127: v1(38.019,97.028) 36.878,98.168 36.878,105.2 39.918,108.24 42.936,108.24 v1(43.101,108.074)
FDCAN1_TX: R127.2 U15.1 | length 43.2
  Top Layer w0.127: v1(33.805,93.8) 34.387,93.218 U15.1@35.761,93.219 ; v1(45.971,111.084) 45.971,112.916 46.596,113.541 48.722,113.541 51.279,116.098 R127.2@51.647,116.098 R127.2@51.694,116.098
  Bottom Layer w0.127: v1(33.805,93.8) 32.128,95.476 32.128,108.786 33.348,110.005 41.476,110.005 42.365,109.116 45.59,109.116 45.87,109.395 45.87,110.983 v1(45.971,111.084)
FDCAN2_RX: R112.2 U10.4 | length 26.8
  Top Layer w0.127: U10.4@35.761,106.171 37.462,106.169 39.164,107.871 42.06,107.871 43.431,109.243 43.431,109.776 43.66,110.005 43.66,111.427 43.431,111.656 43.431,116.822 48.019,121.412 R112.2@51.628,121.412
FDCAN2_TX: SB5.2 U10.1 | length 140
  Top Layer w0.127: v1(22.324,101.013) 22.451,100.886 33.881,100.886 35.354,102.359 U10.1@35.761,102.361 ; v1(80.211,145.082) 80.49,145.082 80.998,144.574 80.998,144.539 SB5.2@81.252,144.285
  L4_SIG w0.102: v1(22.324,101.013) 22.197,101.14 22.197,134.16 21.486,134.871 21.486,141.831 28.542,148.887 29.378,148.887 31.265,150.772 31.265,152.372 32.611,153.718 32.611,156.662 33.719,157.77 42.631,157.77 43.939,156.461 43.939,149.527 48.638,144.828 50.899,144.828 53.058,142.669 57.095,142.669 60.524,139.24 71.727,139.24 73.505,141.018 73.505,143.05 74.013,143.558 77.213,143.558 78.737,145.082 v1(80.211,145.082)
FMC_NBL0: CN5.55 R148.1 U11.A1 | length 118.1
  Top Layer w0.127: CN5.55@31.285,115.521 32.509,115.519 v1(33.246,116.253) ; v1(52.169,113.078) 52.677,113.586 R148.1@53.467,113.588 ; v1(61.897,97.787) 63.561,96.124 67.092,96.124 68.171,97.203 68.171,98.41 U11.A1@67.999,98.585
  L4_SIG w0.102: v1(33.246,116.253) 32.763,116.253 32.611,116.101 32.611,112.138 32.865,111.884 34.922,111.884 35.049,112.011 35.049,114.704 35.278,114.932 38.834,114.932 38.936,114.831 38.936,112.367 39.037,112.265 39.24,112.265 39.342,112.367 39.342,114.831 39.444,114.932 39.647,114.932 39.748,114.831 39.748,112.367 39.85,112.265 40.053,112.265 40.155,112.367 40.155,114.831 40.256,114.932 40.46,114.932 40.561,114.831 40.561,112.367 40.663,112.265 40.866,112.265 40.968,112.367 40.968,114.831 41.069,114.932 41.349,114.932 41.45,114.831 41.45,112.443 41.552,112.342 41.806,112.342 41.882,112.418 41.882,112.824 41.984,112.926 48.108,112.926 52.349,108.684 54.204,108.684 56.185,106.703 57.884,106.703 58.138,106.449 58.138,102.664 58.265,102.537 59.916,102.537 60.018,102.436 60.018,102.131 59.916,102.029 58.265,102.029 58.163,101.928 58.163,101.724 58.265,101.623 59.916,101.623 60.018,101.521 60.018,101.293 59.916,101.191 59.357,101.191 59.256,101.089 59.256,100.886 59.357,100.785 59.916,100.785 60.018,100.683 60.018,100.454 59.916,100.353 59.281,100.353 59.179,100.251 59.179,100.048 59.281,99.946 59.764,99.946 59.865,99.845 59.865,99.464 60.094,99.235 61.796,99.235 61.897,99.134 v1(61.897,97.787)
  Bottom Layer w0.127: v1(33.246,116.253) 30.96,116.253 30.833,116.38 30.833,116.634 30.96,116.761 33.729,116.761 34.008,116.482 39.088,116.482 39.215,116.355 39.215,114.983 39.342,114.856 39.596,114.856 39.723,114.983 39.723,116.355 39.85,116.482 40.104,116.482 40.231,116.355 40.231,113.84 40.358,113.713 40.612,113.713 40.739,113.84 40.739,115.11 40.866,115.237 41.12,115.237 41.247,115.11 41.247,113.84 41.374,113.713 52.042,113.713 52.169,113.586 v1(52.169,113.078)
FMC_NBL1: CN5.53 R149.1 U11.B2 | length 119.8
  Top Layer w0.127: CN5.53@31.285,116.791 32.766,116.789 v1(33.246,117.269) ; v1(54.201,112.619) 54.534,112.951 R149.1@54.534,113.571 ; v1(62.634,97.711) 63.777,96.568 66.876,96.568 67.663,97.356 67.663,98.92 U11.B2@67.249,99.335
  L4_SIG w0.102: v1(33.246,117.269) 32.611,117.269 32.23,116.888 32.23,111.884 32.56,111.554 35.075,111.554 35.557,112.037 35.557,114.45 35.684,114.577 35.913,114.577 36.04,114.45 36.04,112.088 36.167,111.961 36.396,111.961 36.497,112.062 36.497,114.526 36.599,114.628 36.802,114.628 36.904,114.526 36.904,112.062 37.005,111.961 37.208,111.961 37.31,112.062 37.31,114.526 37.412,114.628 37.615,114.628 37.716,114.526 37.716,112.062 37.818,111.961 38.021,111.961 38.123,112.062 38.123,114.526 38.224,114.628 38.428,114.628 38.529,114.526 38.529,112.062 38.631,111.961 42.304,111.961 42.405,112.062 42.405,112.519 42.507,112.621 42.71,112.621 42.812,112.519 42.812,112.062 42.913,111.961 43.116,111.961 43.218,112.062 43.218,112.519 43.32,112.621 43.523,112.621 43.624,112.519 43.624,112.062 43.726,111.961 43.929,111.961 44.031,112.062 44.031,112.519 44.133,112.621 44.336,112.621 44.437,112.519 44.437,112.062 44.539,111.961 44.742,111.961 44.844,112.062 44.844,112.519 44.945,112.621 45.148,112.621 45.25,112.519 45.25,112.062 45.352,111.961 45.555,111.961 45.657,112.062 45.657,112.519 45.758,112.621 45.961,112.621 46.063,112.519 46.063,112.062 46.164,111.961 46.368,111.961 46.469,112.062 46.469,112.484 46.606,112.621 47.983,112.621 52.225,108.379 54.077,108.379 56.058,106.398 57.503,106.398 57.782,106.119 57.782,100.797 59.649,98.93 61.135,98.93 61.389,98.676 61.389,97.432 61.592,97.229 62.481,97.229 62.634,97.381 v1(62.634,97.711)
  Bottom Layer w0.127: v1(33.246,117.269) 31.087,117.269 30.96,117.396 30.96,117.777 31.087,117.904 33.5,117.904 34.008,117.396 42.009,117.396 42.136,117.269 42.136,115.237 42.263,115.11 42.517,115.11 42.644,115.237 42.644,117.269 42.771,117.396 43.025,117.396 43.152,117.269 43.152,114.856 43.533,114.475 54.074,114.475 54.201,114.348 v1(54.201,112.619)
FMC_NE1: CN5.40 R101.2 R171.1 U11.B5 | length 123.2
  Top Layer w0.127: v1(34.389,125.679) CN5.40@36.385,125.681 ; v1(49.502,124.559) 50.061,124 51.186,124 R101.2@51.569,124.384 ; v1(60.366,99.718) R171.1@60.367,98.982 60.406,98.941 64.607,98.941 U11.B5@64.999,99.335
  L4_SIG w0.102: v1(34.389,125.679) 39.721,125.679 39.875,125.524 39.875,125.28 39.774,125.179 38.072,125.179 37.97,125.077 37.97,124.874 38.072,124.772 40.409,124.772 40.51,124.671 40.51,124.468 40.409,124.366 38.072,124.366 37.97,124.264 37.97,124.061 38.072,123.96 40.434,123.96 40.536,123.858 40.536,123.655 40.434,123.553 38.072,123.553 37.97,123.452 37.97,123.248 38.072,123.147 40.434,123.147 40.536,123.045 40.536,122.817 40.434,122.715 39.037,122.715 38.936,122.613 38.936,122.41 39.037,122.309 39.774,122.309 39.875,122.207 39.875,121.206 39.723,121.054 34.11,121.054 34.008,120.952 34.008,115.796 34.211,115.593 41.984,115.593 42.111,115.466 42.111,114.043 42.593,113.561 48.336,113.561 52.603,109.294 54.455,109.294 56.436,107.312 58.595,107.312 59.103,106.804 59.103,104.264 59.306,104.061 60.264,104.061 60.366,103.96 v1(60.366,99.718)
  Bottom Layer w0.127: v1(34.389,125.679) 34.643,125.679 35.049,125.27 44.239,125.27 44.366,125.397 44.366,126.794 44.493,126.921 44.747,126.921 44.874,126.794 44.874,124.127 45.001,124 45.255,124 45.382,124.127 45.382,126.794 45.509,126.921 45.763,126.921 45.89,126.794 45.89,124.127 46.017,124 46.271,124 46.398,124.127 46.398,126.794 46.525,126.921 46.779,126.921 46.906,126.794 46.906,124.127 47.033,124 47.343,124 47.47,124.127 47.47,126.446 47.622,126.601 47.876,126.601 48.003,126.474 48.003,124.102 48.105,124 48.486,124 48.613,124.127 48.613,125.524 48.74,125.651 49.375,125.651 49.502,125.524 v1(49.502,124.559)
FMC_NOE: CN5.33 R94.2 U11.A2 | length 124.4
  Top Layer w0.127: CN5.33@31.285,129.491 v1(33.246,129.489) ; v1(49.502,127.81) 50.137,127.175 51.407,127.175 R94.2@51.572,127.341 ; v1(63.396,97.711) 64.158,96.949 66.672,96.949 67.249,97.528 U11.A2@67.249,98.585
  L4_SIG w0.102: v1(33.246,129.489) 31.951,129.489 31.849,129.388 31.849,129.045 31.951,128.943 33.068,128.943 33.17,128.842 33.17,128.638 33.068,128.537 31.951,128.537 31.849,128.435 31.849,128.232 31.951,128.13 33.068,128.13 33.17,128.029 33.17,127.826 33.068,127.724 31.951,127.724 31.849,127.622 31.849,127.325 31.951,127.224 32.682,127.224 32.784,127.122 32.784,126.919 32.682,126.817 31.951,126.817 31.849,126.716 31.849,126.512 31.951,126.411 32.682,126.411 32.784,126.309 32.784,126.106 32.682,126.004 31.951,126.004 31.849,125.903 31.849,125.7 31.951,125.598 32.682,125.598 32.784,125.496 32.784,125.293 32.682,125.192 31.951,125.192 31.849,125.09 31.849,124.887 31.951,124.785 32.682,124.785 32.784,124.684 32.784,124.48 32.682,124.379 31.951,124.379 31.849,124.277 31.849,124.074 31.951,123.972 32.682,123.972 32.784,123.871 32.784,123.668 32.682,123.566 31.951,123.566 31.849,123.464 31.849,123.193 31.951,123.091 32.509,123.091 32.611,122.989 32.611,122.786 32.509,122.685 31.951,122.685 31.849,122.583 31.849,122.38 31.951,122.278 32.509,122.278 32.611,122.177 32.611,121.973 32.509,121.872 31.951,121.872 31.849,121.77 31.849,111.605 32.23,111.224 35.38,111.224 35.811,111.656 48.517,111.656 52.098,108.074 53.922,108.074 57.478,104.518 57.478,100.67 59.522,98.626 60.703,98.626 61.084,98.245 61.084,97.305 61.465,96.924 63.142,96.924 63.396,97.178 v1(63.396,97.711)
  Bottom Layer w0.127: v1(33.246,129.489) 32.89,129.842 29.69,129.842 29.563,129.715 29.563,129.334 29.69,129.207 32.738,129.207 32.992,128.953 32.992,128.143 33.119,128.016 33.627,128.016 33.754,128.143 33.754,129.207 34.036,129.489 37.645,129.489 38.103,129.032 38.994,129.032 39.121,129.159 39.121,130.193 39.248,130.32 39.502,130.32 39.629,130.193 39.629,129.159 39.756,129.032 40.01,129.032 40.137,129.159 40.137,130.193 40.264,130.32 40.518,130.32 40.645,130.193 40.645,129.159 40.772,129.032 41.026,129.032 41.153,129.159 41.153,130.223 41.28,130.35 41.534,130.35 41.661,130.223 41.661,129.159 41.788,129.032 42.042,129.032 42.169,129.159 42.169,130.223 42.296,130.35 42.55,130.35 42.677,130.223 42.677,129.159 42.804,129.032 43.058,129.032 43.185,129.159 43.185,129.715 43.312,129.842 43.566,129.842 43.693,129.715 43.693,129.159 43.82,129.032 49.375,129.032 49.502,128.905 v1(49.502,127.81)
FMC_NWE: CN5.38 R97.2 U11.G5 | length 123.1
  Top Layer w0.127: v1(34.389,126.794) 34.544,126.949 CN5.38@36.385,126.951 ; v1(49.743,126.096) 49.756,126.096 50.025,126.365 R97.2@51.569,126.365 ; v1(58.753,103.947) 58.753,104.676 59.306,105.23 61.669,105.23 62.608,104.29 64.31,104.29 64.615,103.985 64.615,103.469 64.999,103.086 U11.G5@64.999,103.085
  L4_SIG w0.102: v1(34.389,126.794) 33.856,126.794 33.678,126.616 33.678,125.346 33.779,125.245 37.488,125.245 37.589,125.143 37.589,124.897 37.488,124.795 35.1,124.795 34.999,124.694 34.999,124.49 35.1,124.389 37.488,124.389 37.589,124.287 37.589,124.084 37.488,123.982 35.1,123.982 34.999,123.881 34.999,123.678 35.1,123.576 37.488,123.576 37.589,123.474 37.589,123.271 37.488,123.17 35.1,123.17 34.999,123.068 34.999,122.865 35.1,122.763 37.488,122.763 37.589,122.662 37.589,122.425 37.488,122.324 35.278,122.324 35.151,122.197 35.151,121.994 35.253,121.892 37.539,121.892 37.64,121.79 37.64,121.536 37.513,121.409 33.881,121.409 33.678,121.206 33.678,115.669 34.084,115.263 41.704,115.263 41.806,115.161 41.806,113.916 42.466,113.256 48.209,113.256 52.476,108.989 54.331,108.989 56.312,107.008 58.468,107.008 58.753,106.723 v1(58.753,103.947)
  Bottom Layer w0.127: v1(34.389,126.794) 34.468,126.873 34.955,126.873 35.082,126.746 35.082,125.778 35.209,125.651 35.463,125.651 35.59,125.778 35.59,126.746 35.717,126.873 35.971,126.873 36.098,126.746 36.098,125.778 36.225,125.651 36.479,125.651 36.606,125.778 36.606,126.746 36.733,126.873 36.987,126.873 37.114,126.746 37.114,125.778 37.241,125.651 37.495,125.651 37.622,125.778 37.622,126.746 37.749,126.873 38.019,126.873 38.146,126.746 38.146,125.778 38.273,125.651 38.527,125.651 38.654,125.778 38.654,127.127 38.781,127.254 39.035,127.254 39.162,127.127 39.162,125.778 39.289,125.651 39.543,125.651 39.67,125.778 39.67,127.127 39.797,127.254 40.051,127.254 40.178,127.127 40.178,125.778 40.305,125.651 40.559,125.651 40.686,125.778 40.686,127.127 40.813,127.254 41.067,127.254 41.194,127.127 41.194,125.778 41.321,125.651 41.575,125.651 41.702,125.778 41.702,127.122 41.882,127.302 42.207,127.302 42.334,127.175 42.334,125.778 42.461,125.651 42.715,125.651 42.842,125.778 42.842,127.175 42.969,127.302 43.223,127.302 43.35,127.175 43.35,125.778 43.477,125.651 43.731,125.651 43.858,125.778 43.858,127.175 43.985,127.302 47.757,127.302 48.918,126.144 49.324,126.144 49.693,126.147 v1(49.743,126.096)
